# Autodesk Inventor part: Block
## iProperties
Shininess: 64.0
Length Units: 11269
Angle Units: 11279
Time Units: 11290
Mass Units: 11283
Length Display Precision: 3
Angle Display Precision: 2
Compacted: True
Part Number: Block
Document SubType Name: Modeling
Created: 2006-04
Material: Standard
Designer: IQ-Man
Manufacturer: Standard
Standards Organization: Custom
Density: 0.0
Volumn: 0.0
Area: 0.0
PropertySet Name: Model Information
Control State: 0
Master: False
Checked Out: False
Author: IQ-Man
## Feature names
1. Extrusion1
2. Extrusion2
